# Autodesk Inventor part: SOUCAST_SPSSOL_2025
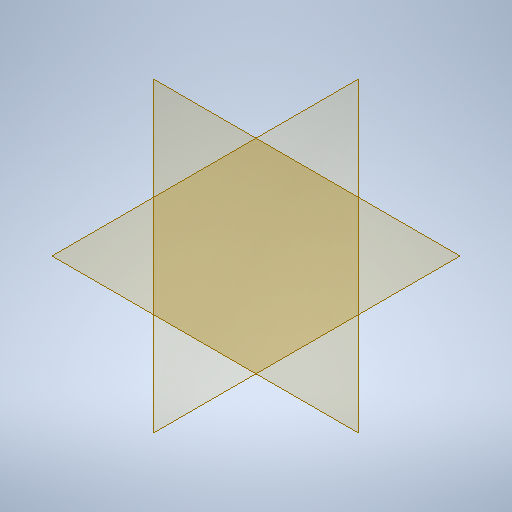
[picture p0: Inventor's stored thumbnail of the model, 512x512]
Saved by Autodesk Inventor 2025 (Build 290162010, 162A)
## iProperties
Part Number: SOUCAST_SPSSOL_2025
Material: OCEL
Document SubType Name: Modeling
Mass: 218.332 g
Surface Area: 74.3212 cm^2
Volume: 27.813 cm^3
Density: 7.85 g/cm^3
Appearance: Tyrkysová(12)
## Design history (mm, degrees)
node "Těleso5"
